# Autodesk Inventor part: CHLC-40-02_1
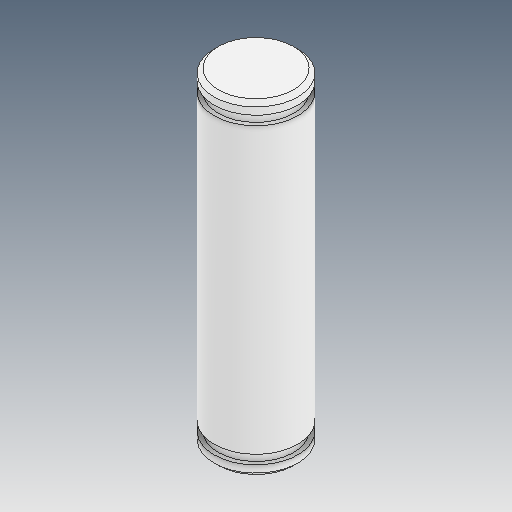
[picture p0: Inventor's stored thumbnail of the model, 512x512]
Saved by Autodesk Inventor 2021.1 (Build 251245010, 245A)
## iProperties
Created: 2021-05
Part Number: CHLC-40-02_1
Material: Ogólny
Document SubType Name: Modeling
Designer: user
Density: 1 g/cm^3
Appearance: Domyślna
Author: user
Revision Number: ÈÎºÎ
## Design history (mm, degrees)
feature "ÊäÈë1"
node "Bryła1"
